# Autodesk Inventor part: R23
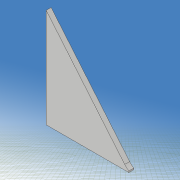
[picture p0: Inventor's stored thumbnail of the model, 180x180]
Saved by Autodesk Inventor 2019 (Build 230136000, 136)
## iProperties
Created: 2021-05
Part Number: R23
Material: 一般
Document SubType Name: Modeling
Designer: kikut
Density: 1 g/cm^3
Appearance: 既定
Mass: 0.06 g
Surface Area: 2.24 cm^2
Volume: 0.06 cm^3
Author: kikut
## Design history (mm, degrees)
sketch "スケッチ1"
  geometry: L1 (80, 60)-(-80, 60); L2 (-80, 60)-(-80, -60); L3 (-80, -60)-(80, -60); L4 (80, -60)-(80, 60); L5 (80, 60)-(-80, -60); L6 (-80, 60)-(80, -60); 1 further point
  constraints: 12 end point, 2 midpoint, 2 parallel, 1 horizontal, 1 perpendicular
  dimensions: "d0" = 160 distance of L2.end L3.end; "d1" = 120 distance of L1.end L2.end
extrude "押し出し1" new body sketch "スケッチ1" stored distance "d2" = 0.6; taper "d3" = 0 deg
sketch "スケッチ2"
  geometry: L1 (-140, 0)-(140, 0) reference; L2 (0, -54)-(20, -30); L3 (0, 54)-(20, 30); L4 (0, -3)-(6.514, -3); L5 (6.514, -3)-(16, -6); L6 (16, -6)-(24, -3); L7 (24, -3)-(33.716, -3); L8 (0, 3)-(6.514, 3); L9 (6.514, 3)-(16, 6); L10 (16, 6)-(24, 3); L11 (24, 3)-(33.716, 3); L12 (0, -98)-(0, 98) reference; L13 (-100, -70)-(100, -70); L14 (100, -70)-(100, 70); L15 (100, 70)-(-100, 70); L16 (-100, 70)-(-100, -70); L17 (-100, -70)-(100, 70); L18 (100, -70)-(-100, 70); A1 r 60 centre (54.312, 28.5) between (0, 54) and (0, 3); A2 r 60 centre (54.312, -28.5) between (0, -3) and (0, -54); A3 r 18.111 centre (18, -12) between (20, -30) and (33.716, -3); A4 r 18.111 centre (18, 12) between (33.716, 3) and (20, 30); 1 further point
  constraints: 32 end point, 8 point on circle, 8 symmetric about line, 4 centre point, 3 horizontal, 2 collinear, 2 midpoint, 2 parallel, 1 perpendicular
  dimensions: "d5" = 60 radius of A1; "d6" = 6 distance of L8.start L4.start; "d7" = 108 distance of L3.start L2.start; "d8" = 0 horizontal distance of L3.start L8.start; "d9" = 60 distance of L3.end L2.end; "d10" = 0 horizontal distance of point (0, 0) L3.start; "d11" = 20 horizontal distance of L3.start L3.end; "d12" = 24 distance of A4.centre A3.centre; "d13" = 6 distance of L11.end L7.end; "d14" = 12 distance of L9.end L5.end; "d15" = 16 distance from line of L12 L5.end; "d16" = 24 distance from line of L6.end L12; "d17" = 200 distance of L14.end L15.end; "d18" = 140 distance of L15.end L13.start; "d30" = 18 distance from line of L12 A4.centre
extrude "押し出し2" cut sketch "スケッチ2" stored distance "d19" = 10; taper "d20" = 0 deg
sketch "スケッチ3"
  geometry: L1 (49.705, -17.97)-(33.948, -15.191); L2 (33.948, -15.191)-(34.295, -13.222); L3 (34.295, -13.222)-(50.052, -16); L4 (50.052, -16)-(49.705, -17.97); L5 (49.705, -17.97)-(34.295, -13.222); L6 (33.948, -15.191)-(50.052, -16); L7 (50.052, 16)-(34.295, 13.222); L8 (34.295, 13.222)-(33.948, 15.191); L9 (33.948, 15.191)-(49.705, 17.97); L10 (49.705, 17.97)-(50.052, 16); L11 (50.052, 16)-(33.948, 15.191); L12 (34.295, 13.222)-(49.705, 17.97); L13 (-112, 0)-(112, 0) reference; L14 (0, -84)-(0, 84) reference; 3 further points
  constraints: 24 end point, 4 midpoint, 4 parallel, 2 perpendicular, 2 symmetric about line
  dimensions: "d21" = 2 distance of L3.end L1.start; "d22" = 2 distance of L9.end L7.start; "d23" = 16 distance of L8.end L9.end; "d24" = 42 distance from line of L14 point (42, 15.596); "d26" = 10 deg angle of L7 L13; "d62" = 16 distance from line of L3.end L13
extrude "押し出し3" join sketch "スケッチ3" distance "d27" = 0.6; taper "d28" = 0 deg
fillet "フィレット1" dims "d31" = 2
fillet "フィレット2" dims "d32" = 1
sketch "スケッチ6"
  geometry: L1 (-20, 60)-(80, 60); L2 (80, 60)-(80, -60); L3 (80, -60)-(-20, -60); L4 (-20, -60)-(-20, 60); L5 (-46.168, 0)-(93.832, 0) reference; L6 (0, -84)-(0, 84) reference; L7 (10, 30)-(20, 30); L8 (20, 30)-(20, 42); L9 (20, 42)-(10, 42); L10 (10, 42)-(10, 30); 1 further point
  constraints: 16 end point, 4 parallel, 2 horizontal, 2 perpendicular, 1 other
  dimensions: "d63" = 120 distance of L3.end L1.start; "d64" = 100 distance of L1.start L1.end; "d65" = 20 distance between parallel lines of L6 L4; "d66" = 10 distance of L8.end L9.end; "d73" = 12 distance of L9.end L7.start; "d74" = 30 distance between parallel lines of L7 L5; "d75" = 30 distance between parallel lines of L10 L4
extrude "押し出し4" cut sketch "スケッチ6" stored distance "d70" = 10; taper "d71" = 0 deg
node "ソリッド1"
